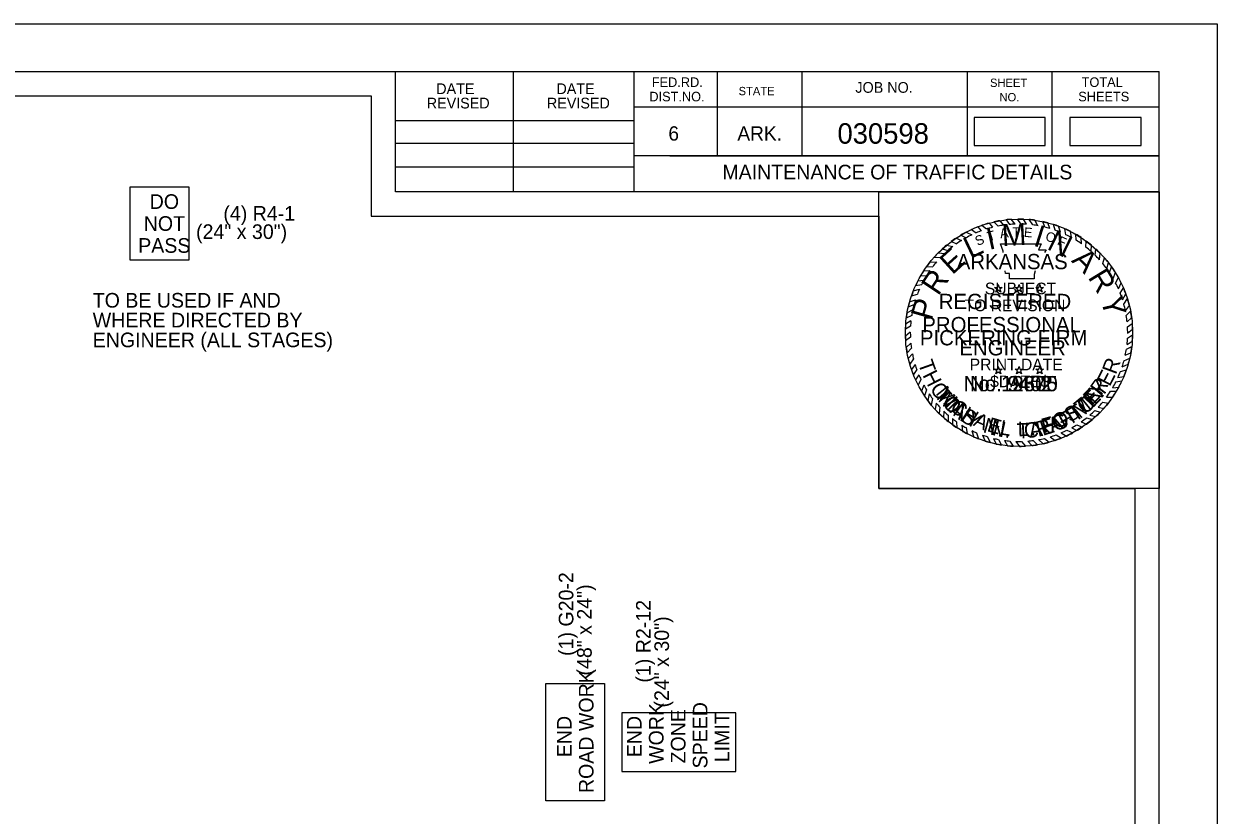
# Model space of a CAD drawing. Extents: x 1368648 to 1927880, y -1037443 to 380209.
# Drawn here: x 1370967.7 to 1371457.1, y 379428.2 to 379752.7 of the extents above; entities that cross this region are included whole.
import ezdxf

# ---------------------------------------------------------------- set-up
doc = ezdxf.new("R2010")
doc.units = 0
for name, color, linetype in [('Default', 7, 'Continuous'), ('Dimensions', 7, 'Continuous'), ('R_Border', 7, 'Continuous'), ('R_Border Notes', 7, 'Continuous'), ('R_No Plot', 7, 'Continuous'), ('R_Signs', 7, 'Continuous'), ('R_Signs_Annot', 7, 'Continuous'), ('STAMP_PE_CRAFTON', 7, 'Continuous'), ('STAMP_PE_FOSTER', 7, 'Continuous'), ('STAMP_PE_SEAL-INFO', 7, 'Continuous'), ('STAMP_PE_TAEGTMEYER', 7, 'Continuous'), ('STAMP_PE_TXT', 7, 'Continuous'), ('STAMP_PRELIMINARY', 7, 'Continuous')]:
    doc.layers.add(name, color=color, linetype=linetype)

msp = doc.modelspace()

# ---------------------------------------------------------------- linework, layer by layer
at = {"layer": 'Default'}
for points in [[(1371357.38, 379702.78), (1371386.55, 379702.78), (1371386.55, 379714.33), (1371357.38, 379714.33)], [(1371396.73, 379702.78), (1371425.9, 379702.78), (1371425.9, 379714.33), (1371396.73, 379714.33)]]:
    msp.add_lwpolyline(points, close=True, dxfattribs=at)
at = {"layer": 'R_Border'}
for p, q in [((1369852.42, 379733.26), (1371433.32, 379733.26)), ((1371120.12, 379683.86), (1371120.12, 379733.26)), ((1371168.52, 379683.86), (1371168.52, 379733.26)), ((1371217.82, 379733.26), (1371217.82, 379683.86)), ((1371252.02, 379733.26), (1371252.02, 379698.56)), ((1371286.72, 379733.26), (1371286.72, 379698.56)), ((1371354.62, 379733.26), (1371354.62, 379698.56)), ((1371389.32, 379733.26), (1371389.32, 379698.56)), ((1371433.32, 378705.96), (1371433.32, 379733.26)), ((1371433.32, 379718.56), (1371217.82, 379718.56)), ((1371433.32, 379718.66), (1371433.32, 379718.66)), ((1371120.12, 379713.16), (1371217.82, 379713.16)), ((1371120.12, 379703.86), (1371217.82, 379703.86)), ((1371433.32, 379698.56), (1371217.82, 379698.56)), ((1371232.62, 379698.56), (1371433.32, 379698.56)), ((1371120.12, 379694.16), (1371217.82, 379694.16)), ((1371433.32, 379683.86), (1371120.12, 379683.86))]:
    msp.add_line(p, q, dxfattribs=at)
at = {"layer": 'R_No Plot'}
for points in [[(1369790.38, 379752.73), (1371457.08, 379752.73), (1371457.08, 378686.04), (1369790.38, 378686.04)], [(1371423.32, 379229.61), (1369862.42, 379229.61), (1369862.42, 379723.26), (1371110.12, 379723.26), (1371110.12, 379673.86), (1371197.82, 379673.86), (1371318.32, 379673.86), (1371318.32, 379562.19), (1371423.32, 379562.19)], [(1369862.42, 379723.26), (1371110.12, 379723.26), (1371110.12, 379673.86), (1371197.82, 379673.86), (1371318.32, 379673.86), (1371318.32, 379562.19), (1371423.32, 379562.19), (1371423.32, 378715.96), (1369862.42, 378715.96)], [(1371318.32, 379683.86), (1371433.32, 379683.86), (1371433.32, 379562.19), (1371318.32, 379562.19)]]:
    msp.add_lwpolyline(points, close=True, dxfattribs=at)
at = {"layer": 'R_Signs'}
for points in [[(1371011.28, 379685.85), (1371035.28, 379685.85), (1371035.28, 379655.85), (1371011.28, 379655.85)], [(1371181.81, 379434.15), (1371181.81, 379482.15), (1371205.81, 379482.15), (1371205.81, 379434.15)], [(1371259.64, 379446.15), (1371259.64, 379470.15), (1371212.88, 379470.15), (1371212.88, 379446.15)]]:
    msp.add_lwpolyline(points, close=True, dxfattribs=at)
at = {"layer": 'STAMP_PE_SEAL-INFO'}
for p, q in [((1371356.34, 379668.42), (1371358.28, 379667.04)), ((1371358.88, 379669.49), (1371360.35, 379667.87)), ((1371360.61, 379670.13), (1371362.52, 379668.61)), ((1371363.57, 379671.04), (1371365.01, 379669.31)), ((1371365.51, 379671.53), (1371367.29, 379669.81)), ((1371367.92, 379672.01), (1371369.42, 379670.17)), ((1371370.5, 379672.38), (1371371.9, 379670.46)), ((1371374.18, 379670.61), (1371372.62, 379672.57)), ((1371376.67, 379670.63), (1371375.27, 379672.68)), ((1371378.96, 379670.53), (1371377.66, 379672.65)), ((1371381.48, 379670.27), (1371380.02, 379672.49)), ((1371383.61, 379669.95), (1371382.33, 379672.23)), ((1371386.42, 379669.36), (1371385.55, 379671.65)), ((1371388.43, 379668.81), (1371387.64, 379671.16)), ((1371390.69, 379668.08), (1371389.99, 379670.48)), ((1371392.78, 379667.28), (1371392.06, 379669.76)), ((1371395.09, 379666.25), (1371394.58, 379668.74)), ((1371347.91, 379663.55), (1371350.18, 379662.53)), ((1371350.01, 379664.88), (1371352.22, 379663.87)), ((1371351.94, 379666.1), (1371354.1, 379664.99)), ((1371354.18, 379667.36), (1371356.5, 379666.23)), ((1371397.32, 379665.11), (1371396.88, 379667.65)), ((1371399.26, 379663.97), (1371399.06, 379666.48)), ((1371401.43, 379662.54), (1371401.27, 379665.12)), ((1371403.23, 379661.21), (1371403.4, 379663.64)), ((1371342.63, 379658.8), (1371345.35, 379658.59)), ((1371344.3, 379660.41), (1371346.6, 379659.72)), ((1371346.02, 379661.92), (1371348.67, 379661.41)), ((1371368.18, 379662.52), (1371384.9, 379662.52)), ((1371368.79, 379660.99), (1371368.18, 379662.52)), ((1371369.31, 379659.5), (1371368.79, 379660.99)), ((1371369.34, 379658.93), (1371369.31, 379659.5)), ((1371384.9, 379662.52), (1371383.78, 379660.07)), ((1371383.78, 379660.07), (1371386.94, 379660.07)), ((1371386.94, 379660.07), (1371386.22, 379658.93)), ((1371405.46, 379659.35), (1371405.56, 379661.96)), ((1371407.03, 379657.88), (1371407.37, 379660.38)), ((1371408.82, 379656.02), (1371409.16, 379658.65)), ((1371339.28, 379655.02), (1371342.03, 379655.13)), ((1371341.01, 379657.08), (1371343.62, 379656.88)), ((1371410.19, 379654.44), (1371410.87, 379656.79)), ((1371411.81, 379652.35), (1371412.49, 379654.85)), ((1371335.49, 379649.45), (1371337.94, 379649.55)), ((1371336.72, 379651.45), (1371339.3, 379651.62)), ((1371337.89, 379653.17), (1371340.42, 379653.15)), ((1371370.3, 379650.38), (1371370.17, 379651.47)), ((1371371.87, 379650.38), (1371370.3, 379650.38)), ((1371371.87, 379648.23), (1371371.87, 379650.38)), ((1371382.1, 379649.92), (1371382.02, 379648.23)), ((1371382.49, 379651.47), (1371382.1, 379649.92)), ((1371412.91, 379650.77), (1371413.8, 379653.09)), ((1371414.45, 379648.29), (1371415.36, 379650.74)), ((1371415.45, 379646.45), (1371416.58, 379648.68)), ((1371332.48, 379643.22), (1371335, 379643.95)), ((1371333.39, 379645.38), (1371335.91, 379645.9)), ((1371334.33, 379647.33), (1371336.83, 379647.65)), ((1371382.02, 379648.23), (1371371.87, 379648.23)), ((1371416.6, 379644.03), (1371417.74, 379646.46)), ((1371417.31, 379642.35), (1371418.62, 379644.52)), ((1371330.94, 379638.68), (1371333.33, 379639.52)), ((1371331.72, 379641.19), (1371334.15, 379641.87)), ((1371418.28, 379639.6), (1371419.63, 379641.98)), ((1371418.82, 379637.78), (1371420.29, 379640.04)), ((1371332.24, 379635.41), (1371329.91, 379634.16)), ((1371330.42, 379636.64), (1371332.77, 379637.6)), ((1371419.48, 379634.99), (1371421.08, 379637.22)), ((1371419.83, 379633.09), (1371421.6, 379634.85)), ((1371331.52, 379630.94), (1371329.33, 379629.53)), ((1371331.81, 379633.11), (1371329.58, 379632)), ((1371420.16, 379630.54), (1371422.02, 379632.22)), ((1371420.32, 379628.45), (1371422.27, 379629.91)), ((1371331.33, 379628.81), (1371329.23, 379627.53)), ((1371331.25, 379626.34), (1371329.23, 379624.67)), ((1371331.28, 379624.31), (1371329.33, 379622.68)), ((1371420.33, 379623.83), (1371422.42, 379625.22)), ((1371420.38, 379625.86), (1371422.41, 379627.47)), ((1371331.45, 379621.83), (1371329.59, 379620.05)), ((1371331.71, 379619.69), (1371329.94, 379617.82)), ((1371419.88, 379619.36), (1371422.09, 379620.46)), ((1371420.13, 379621.3), (1371422.3, 379622.59)), ((1371332.1, 379617.39), (1371330.41, 379615.55)), ((1371332.57, 379615.3), (1371331.01, 379613.22)), ((1371418.88, 379614.6), (1371421.24, 379615.61)), ((1371419.42, 379616.86), (1371421.7, 379617.84)), ((1371333.19, 379613.06), (1371331.72, 379610.97)), ((1371333.89, 379610.95), (1371332.49, 379608.89)), ((1371417.48, 379610.23), (1371419.89, 379610.89)), ((1371418.15, 379612.13), (1371420.6, 379613.14)), ((1371334.73, 379608.81), (1371333.42, 379606.7)), ((1371335.58, 379606.9), (1371334.45, 379604.59)), ((1371336.76, 379604.61), (1371335.8, 379602.16)), ((1371415.6, 379605.98), (1371418.04, 379606.32)), ((1371416.41, 379607.66), (1371418.85, 379608.14)), ((1371337.94, 379602.59), (1371337.02, 379600.23)), ((1371338.95, 379601.03), (1371338.4, 379598.27)), ((1371411.68, 379599.61), (1371414.21, 379599.63)), ((1371413.38, 379602.08), (1371415.77, 379602.05)), ((1371414.24, 379603.49), (1371416.74, 379603.76)), ((1371340.35, 379599.08), (1371339.84, 379596.42)), ((1371341.87, 379597.19), (1371341.44, 379594.59)), ((1371343.39, 379595.5), (1371343.08, 379592.89)), ((1371408.23, 379595.48), (1371410.61, 379595.05)), ((1371410.14, 379597.64), (1371412.45, 379597.24)), ((1371345, 379593.87), (1371344.85, 379591.23)), ((1371346.72, 379592.31), (1371346.7, 379589.67)), ((1371348.52, 379590.84), (1371348.61, 379588.22)), ((1371403.57, 379591.2), (1371405.91, 379590.47)), ((1371404.92, 379592.32), (1371407.28, 379591.67)), ((1371406.95, 379594.18), (1371409.16, 379593.49)), ((1371350.21, 379589.59), (1371350.39, 379587)), ((1371352.35, 379588.18), (1371352.65, 379585.62)), ((1371354.1, 379587.15), (1371354.55, 379584.59)), ((1371356.5, 379585.9), (1371357.29, 379583.3)), ((1371358.37, 379585.06), (1371359.23, 379582.51)), ((1371393.14, 379585.01), (1371395.26, 379583.7)), ((1371395.44, 379586.05), (1371397.86, 379584.99)), ((1371397.48, 379587.12), (1371399.56, 379585.95)), ((1371399.55, 379588.34), (1371401.8, 379587.37)), ((1371401.27, 379589.48), (1371403.46, 379588.54)), ((1371360.83, 379584.1), (1371361.88, 379581.59)), ((1371362.88, 379583.42), (1371364.01, 379580.98)), ((1371365.42, 379582.73), (1371366.48, 379580.4)), ((1371367.4, 379582.3), (1371368.64, 379580.01)), ((1371369.91, 379581.89), (1371371.11, 379579.69)), ((1371372.09, 379581.66), (1371373.46, 379579.51)), ((1371374.51, 379581.52), (1371376.02, 379579.46)), ((1371376.81, 379581.51), (1371378.53, 379579.53)), ((1371379.4, 379581.65), (1371381.03, 379579.75)), ((1371381.6, 379581.88), (1371383.46, 379580.09)), ((1371383.82, 379582.23), (1371385.76, 379580.53)), ((1371386.28, 379582.75), (1371388.17, 379581.12)), ((1371388.58, 379583.37), (1371390.66, 379581.88)), ((1371391.04, 379584.18), (1371393.26, 379582.84))]:
    msp.add_line(p, q, dxfattribs=at)
for radius, start, end in [(46.61, 111.3124, 114.7026), (46.61, 105.2339, 109.0352), (44.57, 104.0352, 107.3615), (46.61, 99.7525, 102.7765), (44.57, 98.258, 101.0329), (46.61, 93.9381, 96.5517), (44.57, 92.1102, 95.0367), (46.61, 87.7298, 90.6707), (44.57, 85.9628, 88.9097), (46.61, 81.9732, 84.8236), (44.57, 79.9264, 82.696), (46.61, 75.3125, 77.9426), (44.57, 73.5575, 76.2314), (46.61, 69.6061, 72.3058), (46.61, 63.1329, 66.2704), (46.61, 123.6199, 126.5906), (44.57, 121.9746, 125.11), (46.61, 117.6544, 120.8099), (44.57, 115.6869, 119.1583), (44.57, 110.3086, 113.1659), (44.57, 67.6248, 70.504), (44.57, 61.1558, 64.3784), (46.61, 56.9003, 60.0942), (44.57, 54.9238, 58.2702), (46.61, 50.3492, 53.7159), (46.61, 135.4021, 138.3031), (44.57, 133.1331, 136.2562), (46.61, 129.7326, 132.5376), (44.57, 127.5297, 130.9683), (44.57, 48.3016, 52.0395), (46.61, 44.3405, 47.3929), (46.61, 141.6056, 144.4486), (44.57, 139.301, 142.5873), (44.57, 42.2212, 45.5512), (44.57, 36.135, 39.5311), (46.61, 38.1247, 41.2316), (46.61, 147.0072, 149.899), (44.57, 145.0197, 148.2104), (44.57, 29.9032, 33.6645), (46.61, 31.9614, 35.4294), (46.61, 25.9391, 29.0125), (46.61, 152.864, 155.5189), (44.57, 156.3402, 159.2319), (44.57, 151.0315, 153.573), (44.57, 23.7732, 27.2211), (46.61, 19.9538, 23.3141), (46.61, 158.4077, 161.0701), (44.57, 162.4331, 165.0013), (44.57, 17.6802, 21.4251), (46.61, 13.8421, 17.4447), (46.61, 170.0003, 172.6878), (46.61, 164.3068, 166.894), (44.57, 167.9048, 170.9039), (44.57, 11.5444, 15.2364), (46.61, 7.5852, 10.8621), (46.61, 175.7409, 178.2066), (44.57, 173.73, 176.4734), (44.57, 5.7599, 9.0606), (46.61, 1.7215, 4.7268), (46.61, 181.7251, 184.1626), (44.57, 179.6454, 182.2633), (44.57, 359.7329, 3.0639), (46.61, 355.7156, 358.9569), (46.61, 187.4204, 190.1927), (44.57, 185.4539, 188.234), (44.57, 348.0778, 351.3435), (44.57, 353.8632, 357.1274), (46.61, 349.8305, 353.0885), (46.61, 193.0369, 195.9973), (44.57, 191.2274, 193.9858), (44.57, 341.777, 345.0925), (46.61, 343.8925, 347.035), (46.61, 198.8967, 201.6281), (44.57, 196.9675, 199.8353), (44.57, 335.6038, 339.1858), (46.61, 337.3837, 340.9933), (46.61, 204.5479, 207.4328), (44.57, 202.7761, 205.4791), (44.57, 208.7883, 211.7934), (44.57, 329.5549, 333.2076), (46.61, 331.4037, 334.9332), (46.61, 210.8636, 213.6571), (44.57, 214.1838, 217.2747), (44.57, 323.5851, 327.4407), (46.61, 325.4405, 328.9872), (46.61, 216.6115, 219.491), (44.57, 220.3909, 223.3056), (44.57, 316.6531, 320.3711), (46.61, 318.2846, 321.8043), (46.61, 222.48, 225.3801), (46.61, 228.3665, 231.348), (44.57, 226.2494, 229.2407), (44.57, 232.229, 234.9336), (44.57, 304.823, 308.5143), (46.61, 306.3721, 310.208), (44.57, 310.7744, 314.3161), (46.61, 312.4518, 315.6633), (46.61, 234.295, 236.9452), (44.57, 238.2223, 240.8353), (46.61, 240.1977, 242.8613), (44.57, 244.3204, 246.9486), (44.57, 292.8745, 296.1185), (46.61, 294.6481, 298.2166), (44.57, 299.0768, 302.1724), (46.61, 300.621, 303.8703), (46.61, 246.576, 249.1558), (44.57, 250.3491, 253.1216), (46.61, 252.5967, 255.3252), (44.57, 256.505, 259.1192), (46.61, 258.4433, 261.1398), (44.57, 262.3783, 265.2012), (44.57, 268.3215, 271.277), (44.57, 274.6157, 277.4486), (46.61, 276.4239, 279.4357), (44.57, 280.3459, 283.5814), (46.61, 282.3199, 285.3702), (44.57, 286.6423, 289.9783), (46.61, 288.5709, 291.9733), (46.61, 264.1978, 267.1009), (46.61, 270.2548, 273.3361)]:
    msp.add_arc((1371375.82, 379626.07), radius, start, end, dxfattribs=at)
at = {"layer": 'STAMP_PE_TXT'}
for p, q in [((1371366.71, 379643.93), (1371365.72, 379644.65)), ((1371365.72, 379644.65), (1371366.95, 379644.65)), ((1371366.34, 379642.76), (1371366.71, 379643.93)), ((1371366.95, 379644.65), (1371367.33, 379645.81)), ((1371367.33, 379645.81), (1371367.71, 379644.65)), ((1371367.71, 379644.65), (1371368.93, 379644.65)), ((1371368.93, 379644.65), (1371367.94, 379643.93)), ((1371367.94, 379643.93), (1371368.32, 379642.76)), ((1371375.2, 379643.93), (1371374.21, 379644.65)), ((1371374.21, 379644.65), (1371375.44, 379644.65)), ((1371374.83, 379642.76), (1371375.2, 379643.93)), ((1371375.44, 379644.65), (1371375.82, 379645.81)), ((1371375.82, 379645.81), (1371376.2, 379644.65)), ((1371376.2, 379644.65), (1371377.42, 379644.65)), ((1371377.42, 379644.65), (1371376.43, 379643.93)), ((1371376.43, 379643.93), (1371376.81, 379642.76)), ((1371383.69, 379643.93), (1371382.7, 379644.65)), ((1371382.7, 379644.65), (1371383.93, 379644.65)), ((1371383.32, 379642.76), (1371383.69, 379643.93)), ((1371383.93, 379644.65), (1371384.31, 379645.81)), ((1371384.31, 379645.81), (1371384.69, 379644.65)), ((1371384.69, 379644.65), (1371385.91, 379644.65)), ((1371385.91, 379644.65), (1371384.92, 379643.93)), ((1371384.92, 379643.93), (1371385.3, 379642.76)), ((1371367.33, 379643.48), (1371366.34, 379642.76)), ((1371368.32, 379642.76), (1371367.33, 379643.48)), ((1371375.82, 379643.48), (1371374.83, 379642.76)), ((1371376.81, 379642.76), (1371375.82, 379643.48)), ((1371384.31, 379643.48), (1371383.32, 379642.76)), ((1371385.3, 379642.76), (1371384.31, 379643.48)), ((1371366.71, 379610.39), (1371365.72, 379611.11)), ((1371365.72, 379611.11), (1371366.95, 379611.11)), ((1371366.34, 379609.22), (1371366.71, 379610.39)), ((1371367.33, 379609.95), (1371366.34, 379609.22)), ((1371366.95, 379611.11), (1371367.33, 379612.28)), ((1371367.33, 379612.28), (1371367.71, 379611.11)), ((1371368.32, 379609.22), (1371367.33, 379609.95)), ((1371367.71, 379611.11), (1371368.93, 379611.11)), ((1371368.93, 379611.11), (1371367.94, 379610.39)), ((1371367.94, 379610.39), (1371368.32, 379609.22)), ((1371375.2, 379610.39), (1371374.21, 379611.11)), ((1371374.21, 379611.11), (1371375.44, 379611.11)), ((1371374.83, 379609.22), (1371375.2, 379610.39)), ((1371375.82, 379609.95), (1371374.83, 379609.22)), ((1371375.44, 379611.11), (1371375.82, 379612.28)), ((1371375.82, 379612.28), (1371376.2, 379611.11)), ((1371376.81, 379609.22), (1371375.82, 379609.95)), ((1371376.2, 379611.11), (1371377.42, 379611.11)), ((1371377.42, 379611.11), (1371376.43, 379610.39)), ((1371376.43, 379610.39), (1371376.81, 379609.22)), ((1371383.69, 379610.39), (1371382.7, 379611.11)), ((1371382.7, 379611.11), (1371383.93, 379611.11)), ((1371383.32, 379609.22), (1371383.69, 379610.39)), ((1371384.31, 379609.95), (1371383.32, 379609.22)), ((1371383.93, 379611.11), (1371384.31, 379612.28)), ((1371384.31, 379612.28), (1371384.69, 379611.11)), ((1371385.3, 379609.22), (1371384.31, 379609.95)), ((1371384.69, 379611.11), (1371385.91, 379611.11)), ((1371385.91, 379611.11), (1371384.92, 379610.39)), ((1371384.92, 379610.39), (1371385.3, 379609.22))]:
    msp.add_line(p, q, dxfattribs=at)
at = {"layer": 'STAMP_PRELIMINARY'}
msp.add_circle((1371375.82, 379626.07), 46.61, dxfattribs=at)

# ---------------------------------------------------------------- texts
at = {"layer": 'Dimensions'}
for s, p in [('TO BE USED IF AND', (1370995.93, 379636.37)), ('WHERE DIRECTED BY', (1370995.93, 379628.24)), ('ENGINEER (ALL STAGES)', (1370995.93, 379620.12))]:
    msp.add_text(s, height=6, dxfattribs=at).set_placement(p)
at = {"layer": 'R_Border'}
for s, height, p in [('DATE', 4.396, (1371136.81, 379723.94)), ('DATE', 4.396, (1371186.11, 379723.94)), ('FED.RD.', 3.91, (1371225.22, 379726.86)), ('STATE', 3.42, (1371260.82, 379723.46)), ('JOB NO.', 4.396, (1371308.72, 379724.46)), ('SHEET', 3.42, (1371363.92, 379726.86)), ('TOTAL', 3.91, (1371401.52, 379726.86)), ('REVISED', 4.396, (1371132.91, 379718.04)), ('REVISED', 4.396, (1371182.21, 379718.04)), ('DIST.NO.', 3.91, (1371224.22, 379720.96)), ('NO.', 3.42, (1371367.82, 379720.96)), ('SHEETS', 3.91, (1371400.12, 379720.96)), ('6', 5.86, (1371232.02, 379704.86)), ('ARK.', 5.861, (1371260.32, 379704.86))]:
    msp.add_text(s, height=height, dxfattribs=at).set_placement(p)
at = {"layer": 'R_Border Notes'}
for s, height, p in [('030598', 8.4, (1371301.37, 379703.58)), ('MAINTENANCE OF TRAFFIC DETAILS', 6, (1371254.16, 379688.95))]:
    msp.add_text(s, height=height, dxfattribs=at).set_placement(p)
at = {"layer": 'R_Signs'}
for s, p in [('DO', (1371019.29, 379676.85)), ('NOT', (1371016.85, 379667.85)), ('PASS', (1371014.58, 379658.85))]:
    msp.add_text(s, height=6, dxfattribs=at).set_placement(p)
for s, p in [('ROAD WORK', (1371201.31, 379437.28)), ('WORK', (1371230.04, 379449.24)), ('SPEED', (1371248.04, 379447.37)), ('END', (1371192.31, 379451.99)), ('END', (1371221.04, 379451.97)), ('ZONE', (1371239.04, 379449.43)), ('LIMIT', (1371257.04, 379449.93))]:
    msp.add_text(s, height=6, rotation=90, dxfattribs=at).set_placement(p)
at = {"layer": 'R_Signs_Annot'}
for s, p in [('(4) R4-1', (1371049.51, 379672.02)), ('(24" x 30")', (1371038.31, 379664.51))]:
    msp.add_text(s, height=6, dxfattribs=at).set_placement(p)
for s, p in [('(1) G20-2', (1371193.05, 379493.52)), ('(48" x 24")', (1371200.57, 379485.49)), ('(1) R2-12', (1371224.76, 379482.59)), ('(24" x 30")', (1371232.27, 379472.38))]:
    msp.add_text(s, height=6, rotation=90, dxfattribs=at).set_placement(p)
at = {"layer": 'STAMP_PE_CRAFTON'}
for s, rotation, p in [('T', 310.7442, (1371340.65, 379600.56)), ('O', 317.6422, (1371343.98, 379596.5)), ('O', 41.8391, (1371402.99, 379592.27)), ('N', 49.2411, (1371407.23, 379596.18)), ('N', 324.4537, (1371348.21, 379592.58)), ('T', 34.1136, (1371398.7, 379589.26)), ('Y', 331.1686, (1371353.38, 379589)), ('N', 347.4752, (1371363.65, 379584.42)), ('R', 14.8189, (1371383.66, 379583.35)), ('A', 20.5125, (1371389.22, 379584.85)), ('F', 28.7821, (1371394.12, 379586.72)), ('C', 6.0117, (1371378.17, 379582.77)), ('.', 356.8926, (1371369.8, 379583.03))]:
    msp.add_text(s, height=6.25, rotation=rotation, dxfattribs=at).set_placement(p)
msp.add_text('No. 12370', height=6.25, dxfattribs=at).set_placement((1371353.13, 379602.05))
at = {"layer": 'STAMP_PE_FOSTER'}
msp.add_text('No. 9402', height=6.25, dxfattribs=at).set_placement((1371355.75, 379602.05))
for s, rotation, p in [('R', 54.5031, (1371409.44, 379600.12)), ('M', 308.339, (1371341.4, 379601.18)), ('I', 314.1842, (1371345.39, 379596.49)), ('T', 39.4194, (1371401.53, 379592.27)), ('E', 46.9613, (1371405.82, 379596.02)), ('C', 319.8733, (1371347.16, 379594.72)), ('H', 327.7235, (1371351.8, 379591.04)), ('S', 31.7234, (1371396.77, 379589.13)), ('A', 335.7276, (1371356.71, 379588.13)), ('E', 343.5779, (1371362.39, 379585.78)), ('L', 350.8115, (1371367.69, 379584.39)), ('F', 15.8691, (1371385.99, 379584.84)), ('O', 23.719, (1371391.21, 379586.48)), ('L', 1.2666, (1371375.38, 379583.61)), ('.', 6.8035, (1371380.62, 379583.9))]:
    msp.add_text(s, height=6, rotation=rotation, dxfattribs=at).set_placement(p)
at = {"layer": 'STAMP_PE_TAEGTMEYER'}
for s, rotation, p in [('T', 289.646, (1371334.29, 379613.62)), ('R', 69.57, (1371415.54, 379608.64)), ('H', 296.7339, (1371336.09, 379608.7)), ('E', 63.0984, (1371413.05, 379603.73)), ('O', 303.7708, (1371339.05, 379603.16)), ('Y', 53.9986, (1371409.7, 379599.03)), ('M', 314.2033, (1371342.33, 379598.4)), ('E', 46.8094, (1371406.01, 379594.95)), ('A', 321.0594, (1371347.14, 379593.58)), ('S', 327.8239, (1371351.27, 379590.36)), ('T', 31.466, (1371396.32, 379587.84)), ('M', 39.3, (1371400.81, 379590.56)), ('N', 344.2727, (1371360.75, 379585.33)), ('E', 17.6836, (1371385.57, 379583.73)), ('G', 23.3052, (1371390.82, 379585.38)), ('T', 3.0061, (1371375.14, 379582.67)), ('A', 8.9826, (1371380.37, 379582.95)), ('.', 350.6464, (1371366.81, 379583.67))]:
    msp.add_text(s, height=6.25, rotation=rotation, dxfattribs=at).set_placement(p)
msp.add_text('No. 19605', height=6.25, dxfattribs=at).set_placement((1371353.13, 379602.05))
at = {"layer": 'STAMP_PE_TXT'}
for s, rotation, p in [('A', 9.0679, (1371368.24, 379664.71)), ('T', 1.8248, (1371373.17, 379665.36)), ('E', 355.2002, (1371377.72, 379665.4)), ('S', 23.5541, (1371358.81, 379661.59)), ('T', 16.311, (1371363.43, 379663.45)), ('O', 342.2506, (1371386.35, 379664.02)), ('F', 335.0075, (1371391.18, 379662.33))]:
    msp.add_text(s, height=3.91, rotation=rotation, dxfattribs=at).set_placement(p)
for s, p in [('ARKANSAS', (1371350.28, 379652.12)), ('REGISTERED', (1371342.9, 379635.77)), ('PROFESSIONAL', (1371336.16, 379626.27)), ('ENGINEER', (1371351.36, 379616.76))]:
    msp.add_text(s, height=6.25, dxfattribs=at).set_placement(p)
at = {"layer": 'STAMP_PRELIMINARY'}
for s, rotation, p in [('I', 12.5248, (1371363.51, 379660)), ('M', 3.1074, (1371369, 379661.55)), ('I', 342.3164, (1371381.33, 379661.88)), ('N', 333.9382, (1371386.87, 379660.51)), ('L', 25.513, (1371355.86, 379656.21)), ('E', 42.3578, (1371348.45, 379649.55)), ('A', 315.6579, (1371397.04, 379655.39)), ('R', 56.2292, (1371342.67, 379640.89)), ('R', 301.3831, (1371403.88, 379648.82)), ('P', 73.913, (1371339.92, 379630.77)), ('Y', 283.2593, (1371409.33, 379639.88))]:
    msp.add_text(s, height=9, rotation=rotation, dxfattribs=at).set_placement(p)
for s, height, p in [('SUBJECT', 4.8, (1371361.82, 379641.81)), ('TO REVISION', 4.8, (1371353.49, 379634.89)), ('PICKERING FIRM', 6.25, (1371335.18, 379620.88)), ('PRINT DATE', 4.8, (1371355.6, 379610.65)), ('$DATE$', 4.8, (1371363.99, 379603.72))]:
    msp.add_text(s, height=height, dxfattribs=at).set_placement(p)

doc.saveas('drawing.dxf')
